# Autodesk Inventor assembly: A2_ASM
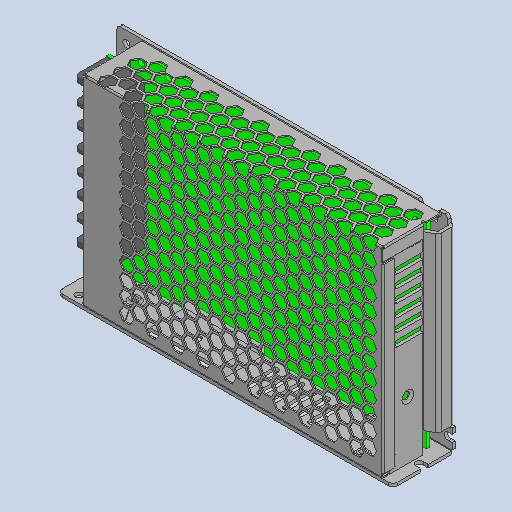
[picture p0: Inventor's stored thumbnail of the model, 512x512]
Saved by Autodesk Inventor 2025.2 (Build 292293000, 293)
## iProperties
Created: 2025-04
Part Number: A2_ASM
Description: NOT SPECIFIED
Document SubType Name: Assembly
Designer: BennF
Author: BennF
Revision Number: 4LAST_VERSION
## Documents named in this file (5)
- C:\Users\BennF\Nextcloud\Benutzer\CNC JarBeRi\existing parts\Electronics\Powersupply LRS-150-24\LRS-150(230808)\LRS-150(230808)\A2_ASM.iam
- C:\Users\BennF\Nextcloud\Benutzer\CNC JarBeRi\existing parts\Electronics\Powersupply LRS-150-24\LRS-150(230808)\LRS-150(230808)\_X2_4E0A84CB_X0_.ipt
- C:\Users\BennF\Nextcloud\Benutzer\CNC JarBeRi\existing parts\Electronics\Powersupply LRS-150-24\LRS-150(230808)\LRS-150(230808)\_X2_5E955EA7_X0__ASM.iam
- C:\Users\BennF\Nextcloud\Benutzer\CNC JarBeRi\existing parts\Electronics\Powersupply LRS-150-24\LRS-150(230808)\LRS-150(230808)\HS_ASM.iam
- C:\Users\BennF\Nextcloud\Benutzer\CNC JarBeRi\existing parts\Electronics\Powersupply LRS-150-24\LRS-150(230808)\LRS-150(230808)\A1-112870_ASM.iam
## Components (4 placed, 4 different names)
1. _X2_4E0A84CB_X0__17
2. _X2_5E955EA7_X0__ASM_21 [sub-assembly]
3. HS_ASM_24 [sub-assembly]
4. A1-112870_ASM_27 [sub-assembly]
